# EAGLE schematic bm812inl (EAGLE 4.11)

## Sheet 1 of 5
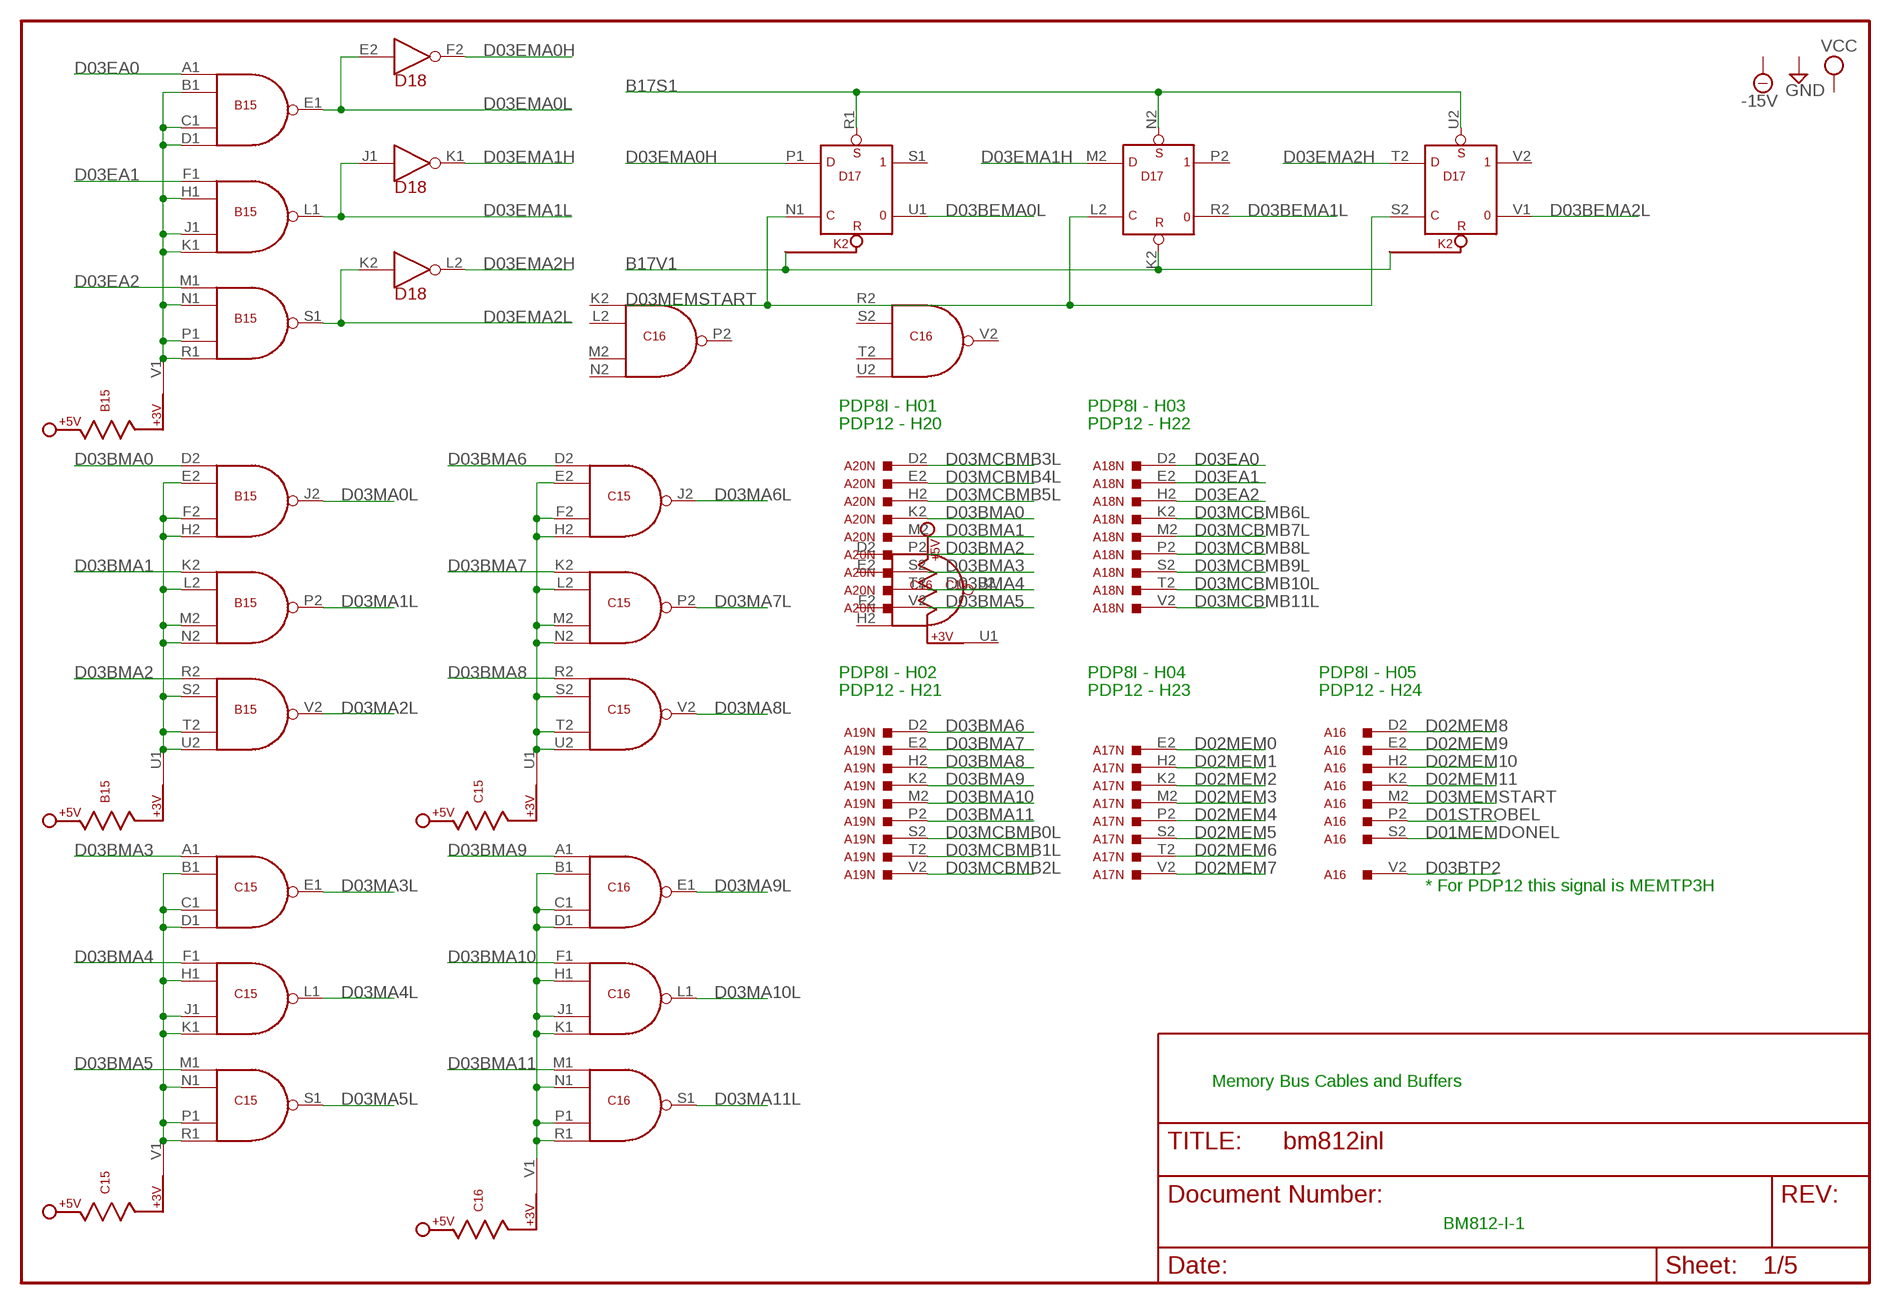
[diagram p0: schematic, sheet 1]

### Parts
A16  M903  [H807]
A17N  M903  [H807]
A18N  M903  [H807]
A19N  M903  [H807]
A20N  M903  [H807]
B15  M627  [H807]
C15  M627  [H807]
C16  M627  [H807]
D17  M206X  [H807]
D18  M111  [H807]

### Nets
B17S1: D17.N2(K2:S) D17.R1(K2B:S) D17.U2(K2C:S) ; also sheet 3,4
B17V1: D17.K2(K2:R) ; also sheet 3,4
D01MEMDONEL: A16.S2 ; also sheet 4
D01STROBEL: A16.P2 ; also sheet 4
D02MEM0: A17N.E2 ; also sheet 3
D02MEM1: A17N.H2 ; also sheet 3
D02MEM2: A17N.K2 ; also sheet 3
D02MEM3: A17N.M2 ; also sheet 3
D02MEM4: A17N.P2 ; also sheet 3
D02MEM5: A17N.S2 ; also sheet 3
D02MEM6: A17N.T2 ; also sheet 3
D02MEM7: A17N.V2 ; also sheet 3
D02MEM8: A16.D2 ; also sheet 3
D02MEM9: A16.E2 ; also sheet 3
D02MEM10: A16.H2 ; also sheet 3
D02MEM11: A16.K2 ; also sheet 3
D03BEMA0L: D17.U1 ; also sheet 5
D03BEMA1L: D17.R2 ; also sheet 5
D03BEMA2L: D17.V1 ; also sheet 5
D03BMA0: A20N.K2 B15.D2(IN1)
D03BMA1: A20N.M2 B15.K2(IN1)
D03BMA2: A20N.P2 B15.R2(IN1)
D03BMA3: A20N.S2 C15.A1(IN1)
D03BMA4: A20N.T2 C15.F1(IN1)
D03BMA5: A20N.V2 C15.M1(IN1)
D03BMA6: A19N.D2 C15.D2(IN1)
D03BMA7: A19N.E2 C15.K2(IN1)
D03BMA8: A19N.H2 C15.R2(IN1)
D03BMA9: A19N.K2 C16.A1(IN1)
D03BMA10: A19N.M2 C16.F1(IN1)
D03BMA11: A19N.P2 C16.M1(IN1)
D03BTP2: A16.V2 ; also sheet 4
D03EA0: A18N.D2 B15.A1(IN1)
D03EA1: A18N.E2 B15.F1(IN1)
D03EA2: A18N.H2 B15.M1(IN1)
D03EMA0H: D17.P1(K2B:D) D18.F2(5:OUT) ; also sheet 4
D03EMA0L: B15.E1(OUT) D18.E2(5:IN) ; also sheet 4
D03EMA1H: D17.M2(K2:D) D18.K1(6:OUT) ; also sheet 4
D03EMA1L: B15.L1(OUT) D18.J1(6:IN) ; also sheet 4
D03EMA2H: D17.T2(K2C:D) D18.L2(9:OUT) ; also sheet 4
D03EMA2L: B15.S1(OUT) D18.K2(9:IN) ; also sheet 4
D03MA0L: B15.J2(OUT) ; also sheet 5
D03MA1L: B15.P2(OUT) ; also sheet 5
D03MA2L: B15.V2(OUT) ; also sheet 5
D03MA3L: C15.E1(OUT) ; also sheet 5
D03MA4L: C15.L1(OUT) ; also sheet 5
D03MA5L: C15.S1(OUT) ; also sheet 5
D03MA6L: C15.J2(OUT) ; also sheet 5
D03MA7L: C15.P2(OUT) ; also sheet 5
D03MA8L: C15.V2(OUT) ; also sheet 5
D03MA9L: C16.E1(OUT) ; also sheet 5
D03MA10L: C16.L1(OUT) ; also sheet 5
D03MA11L: C16.S1(OUT) ; also sheet 5
D03MCBMB0L: A19N.S2 ; also sheet 3
D03MCBMB1L: A19N.T2 ; also sheet 3
D03MCBMB2L: A19N.V2 ; also sheet 3
D03MCBMB3L: A20N.D2 ; also sheet 3
D03MCBMB4L: A20N.E2 ; also sheet 3
D03MCBMB5L: A20N.H2 ; also sheet 3
D03MCBMB6L: A18N.K2 ; also sheet 3
D03MCBMB7L: A18N.M2 ; also sheet 3
D03MCBMB8L: A18N.P2 ; also sheet 3
D03MCBMB9L: A18N.S2 ; also sheet 3
D03MCBMB10L: A18N.T2 ; also sheet 3
D03MCBMB11L: A18N.V2 ; also sheet 3
D03MEMSTART: A16.M2 D17.L2(K2:C) D17.N1(K2B:C) D17.S2(K2C:C) ; also sheet 4
N$1: B15.B1(IN2) B15.C1(IN3) B15.D1(IN4) B15.H1(IN2) B15.J1(IN3) B15.K1(IN4) B15.N1(IN2) B15.P1(IN3) B15.R1(IN4) B15.V1
N$2: B15.E2(IN2) B15.F2(IN3) B15.H2(IN4) B15.L2(IN2) B15.M2(IN3) B15.N2(IN4) B15.S2(IN2) B15.T2(IN3) B15.U1 B15.U2(IN4)
N$4: C15.B1(IN2) C15.C1(IN3) C15.D1(IN4) C15.H1(IN2) C15.J1(IN3) C15.K1(IN4) C15.N1(IN2) C15.P1(IN3) C15.R1(IN4) C15.V1
N$6: C15.E2(IN2) C15.F2(IN3) C15.H2(IN4) C15.L2(IN2) C15.M2(IN3) C15.N2(IN4) C15.S2(IN2) C15.T2(IN3) C15.U1 C15.U2(IN4)
N$122: C16.B1(IN2) C16.C1(IN3) C16.D1(IN4) C16.H1(IN2) C16.J1(IN3) C16.K1(IN4) C16.N1(IN2) C16.P1(IN3) C16.R1(IN4) C16.V1
Unconnected: A16.B1 A16.D1 A16.E1 A16.H1 A16.J1 A16.L1 A16.M1 A16.P1 A16.S1 A16.T2 A17N.B1 A17N.D1 A17N.D2 A17N.E1 A17N.H1 A17N.J1 A17N.L1 A17N.M1 A17N.P1 A17N.S1 A18N.B1 A18N.D1 A18N.E1 A18N.H1 A18N.J1 A18N.L1 A18N.M1 A18N.P1 A18N.S1 A19N.B1 A19N.D1 A19N.E1 A19N.H1 A19N.J1 A19N.L1 A19N.M1 A19N.P1 A19N.S1 A20N.B1 A20N.D1 A20N.E1 A20N.H1 A20N.J1 A20N.L1 A20N.M1 A20N.P1 A20N.S1 D17.D2(A1B:C) D17.E2(A1B:D) D17.F2(A1B:S) D17.H1(A1C:C) D17.H2 D17.J1(A1C:D) D17.J2 D17.K1(A1C:S) D17.L1 D17.M1 D18.L1(8:IN) D18.M1(8:OUT) D18.N1(10:IN) D18.P1(10:OUT) D18.P2(13:IN) D18.R2(13:OUT) D18.S2(15:IN) D18.T2(15:OUT) D18.U1(14:OUT) D18.U2(16:IN) D18.V1(14:IN) D18.V2(16:OUT)

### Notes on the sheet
- PDP8I - H01 | PDP8I - H03
- PDP12 - H20 | PDP12 - H22
- PDP8I - H02 | PDP8I - H04 | PDP8I - H05
- PDP12 - H21 | PDP12 - H23 | PDP12 - H24
- * For PDP12 this signal is MEMTP3H
- Memory Bus Cables and Buffers
- BM812-I-1

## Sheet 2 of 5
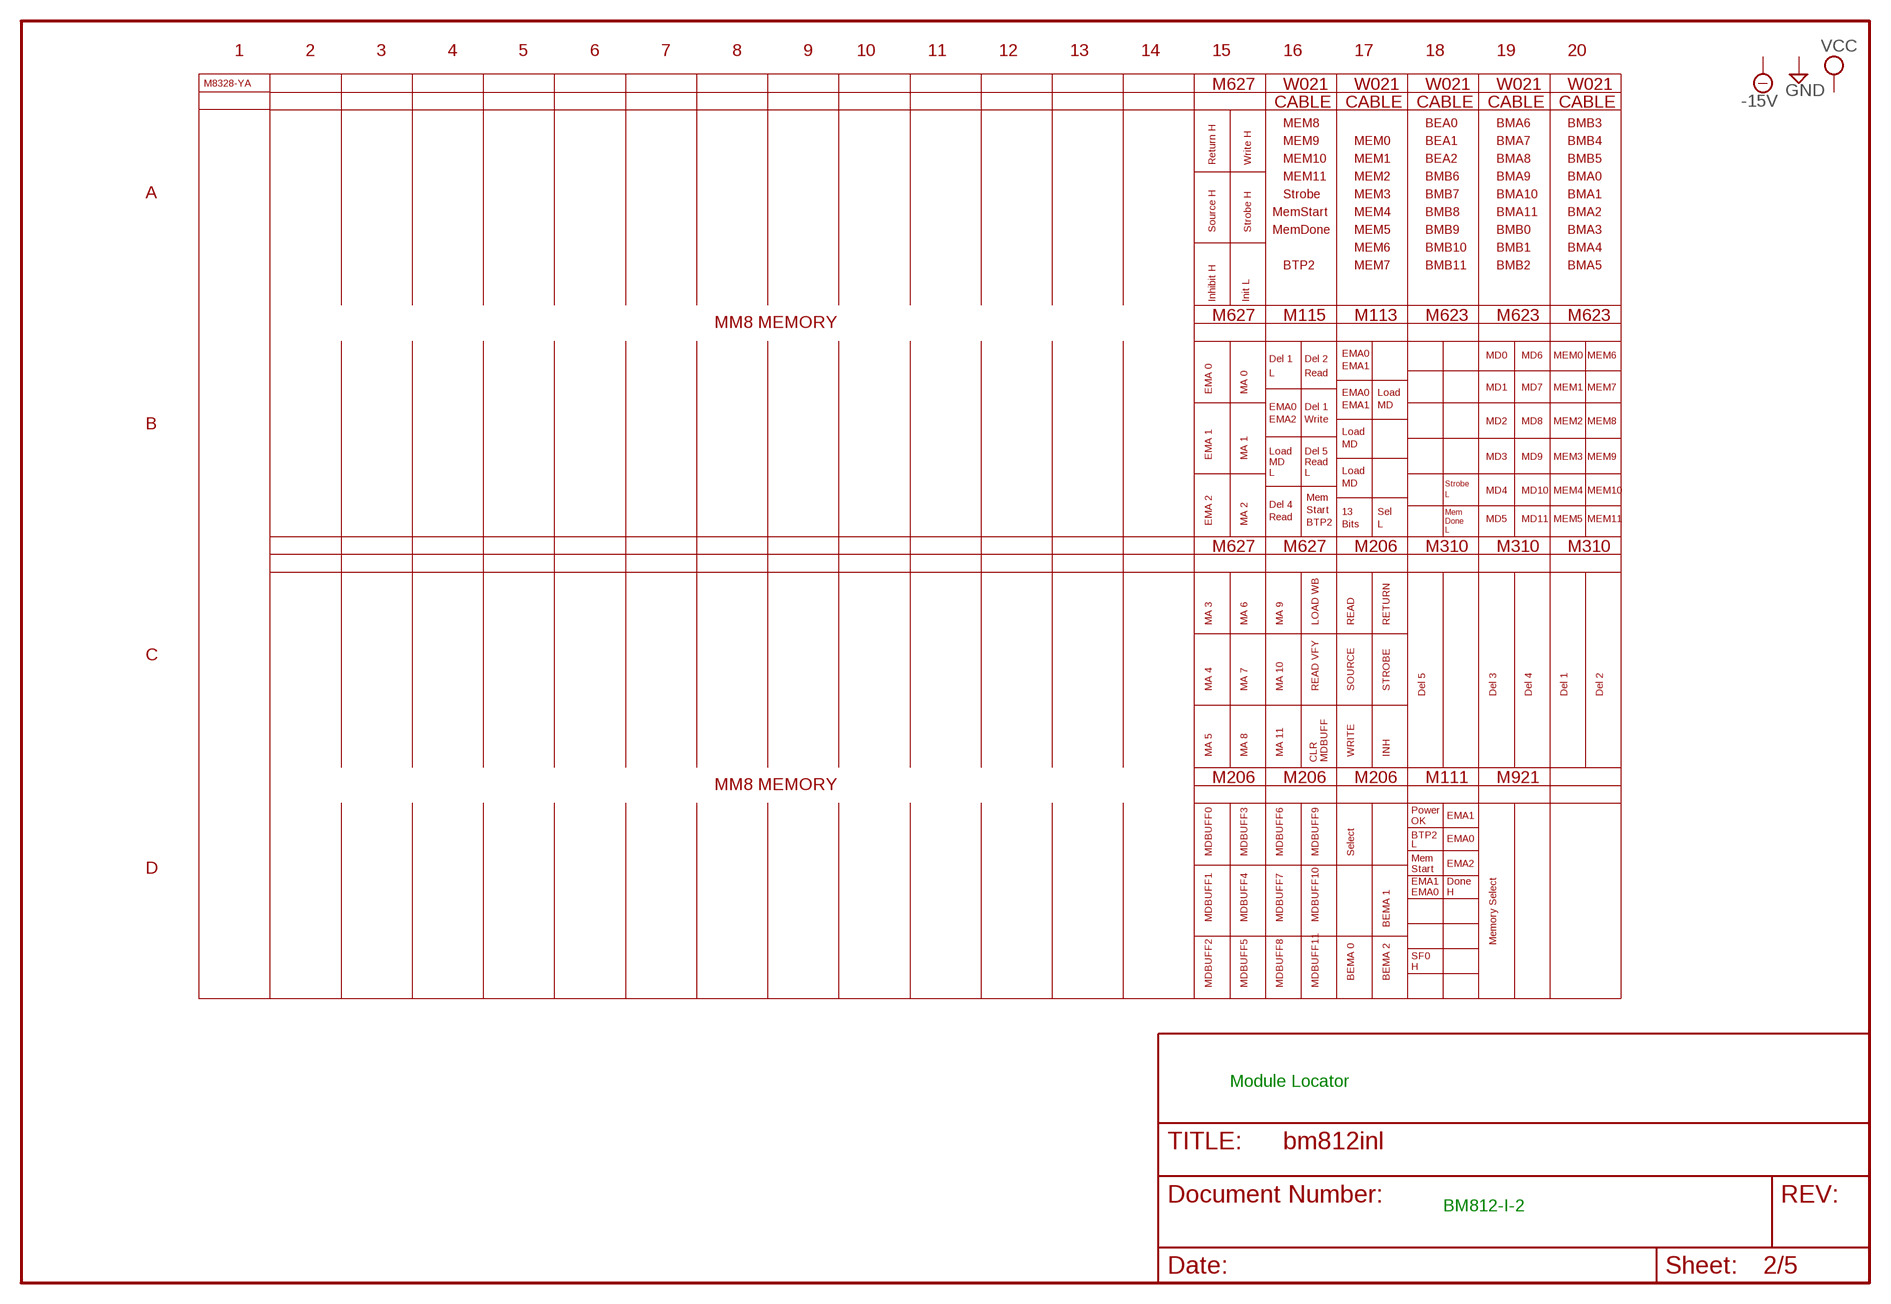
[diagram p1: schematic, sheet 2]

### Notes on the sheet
- 1 | 2 | 3 | 4 | 5 | 6 | 7 | 8 | 9 | 10 | 11 | 12 | 13 | 14 | 15 | 16 | 17 | 18 | 19 | 20
- M8328-YA
- M627 | W021 | W021 | W021 | W021 | W021
- CABLE | CABLE | CABLE | CABLE | CABLE
- MEM8 | BEA0 | BMA6 | BMB3
- MEM9 | MEM0 | BEA1 | BMA7 | BMB4
- Return H | Write H | MEM10 | MEM1 | BEA2 | BMA8 | BMB5
- MEM11 | MEM2 | BMB6 | BMA9 | BMA0
- A | Strobe | MEM3 | BMB7 | BMA10 | BMA1
- MemStart | MEM4 | BMB8 | BMA11 | BMA2
- Source H | Strobe H | MemDone | MEM5 | BMB9 | BMB0 | BMA3
- MEM6 | BMB10 | BMB1 | BMA4
- BTP2 | MEM7 | BMB11 | BMB2 | BMA5
- Inhibit H | Init L
- M627 | M115 | M113 | M623 | M623 | M623
- MM8 MEMORY
- EMA0 | MD0 | MD6 | MEM0 | MEM6
- Del 1 | Del 2
- EMA1
- L | Read
- MD1 | MD7 | MEM1 | MEM7
- EMA 0 | MA 0 | EMA0 | Load
- EMA0 | Del 1 | EMA1 | MD
- EMA2 | Write | MD2 | MD8 | MEM2 | MEM8
- B
- Load
- MD
- Load | Del 5
- EMA 1 | MA 1 | MD3 | MD9 | MEM3 | MEM9
- MD | Read
- L | L | Load
- MD | Strobe
- MD4 | MD10 | MEM4 | MEM10
- L
- Mem
- Del 4
- Start | 13 | Sel | Mem
- Read | MD5 | MD11 | MEM5 | MEM11
- EMA 2 | MA 2 | BTP2 | Done
- Bits | L
- L
- M627 | M627 | M206 | M310 | M310 | M310
- MA 3 | MA 6 | MA 9 | LOAD WB | READ | RETURN
- C
- MA 4 | MA 7 | MA 10 | READ VFY | SOURCE | STROBE
- Del 5 | Del 3 | Del 4 | Del 1 | Del 2
- MA 5 | MA 8 | MA 11 | WRITE | INH
- CLR | MDBUFF
- M206 | M206 | M206 | M111 | M921
- MM8 MEMORY
- Power
- EMA1
- OK
- BTP2
- EMA0
- L
- MDBUFF0 | MDBUFF3 | MDBUFF6 | MDBUFF9 | Select
- Mem
- EMA2
- D | Start
- EMA1 | Done
- EMA0 | H
- MDBUFF1 | MDBUFF4 | MDBUFF7 | MDBUFF10
- BEMA 1
- Memory Select
- SF0
- H
- BEMA 0 | BEMA 2
- MDBUFF2 | MDBUFF5 | MDBUFF8 | MDBUFF11
- Module Locator
- BM812-I-2

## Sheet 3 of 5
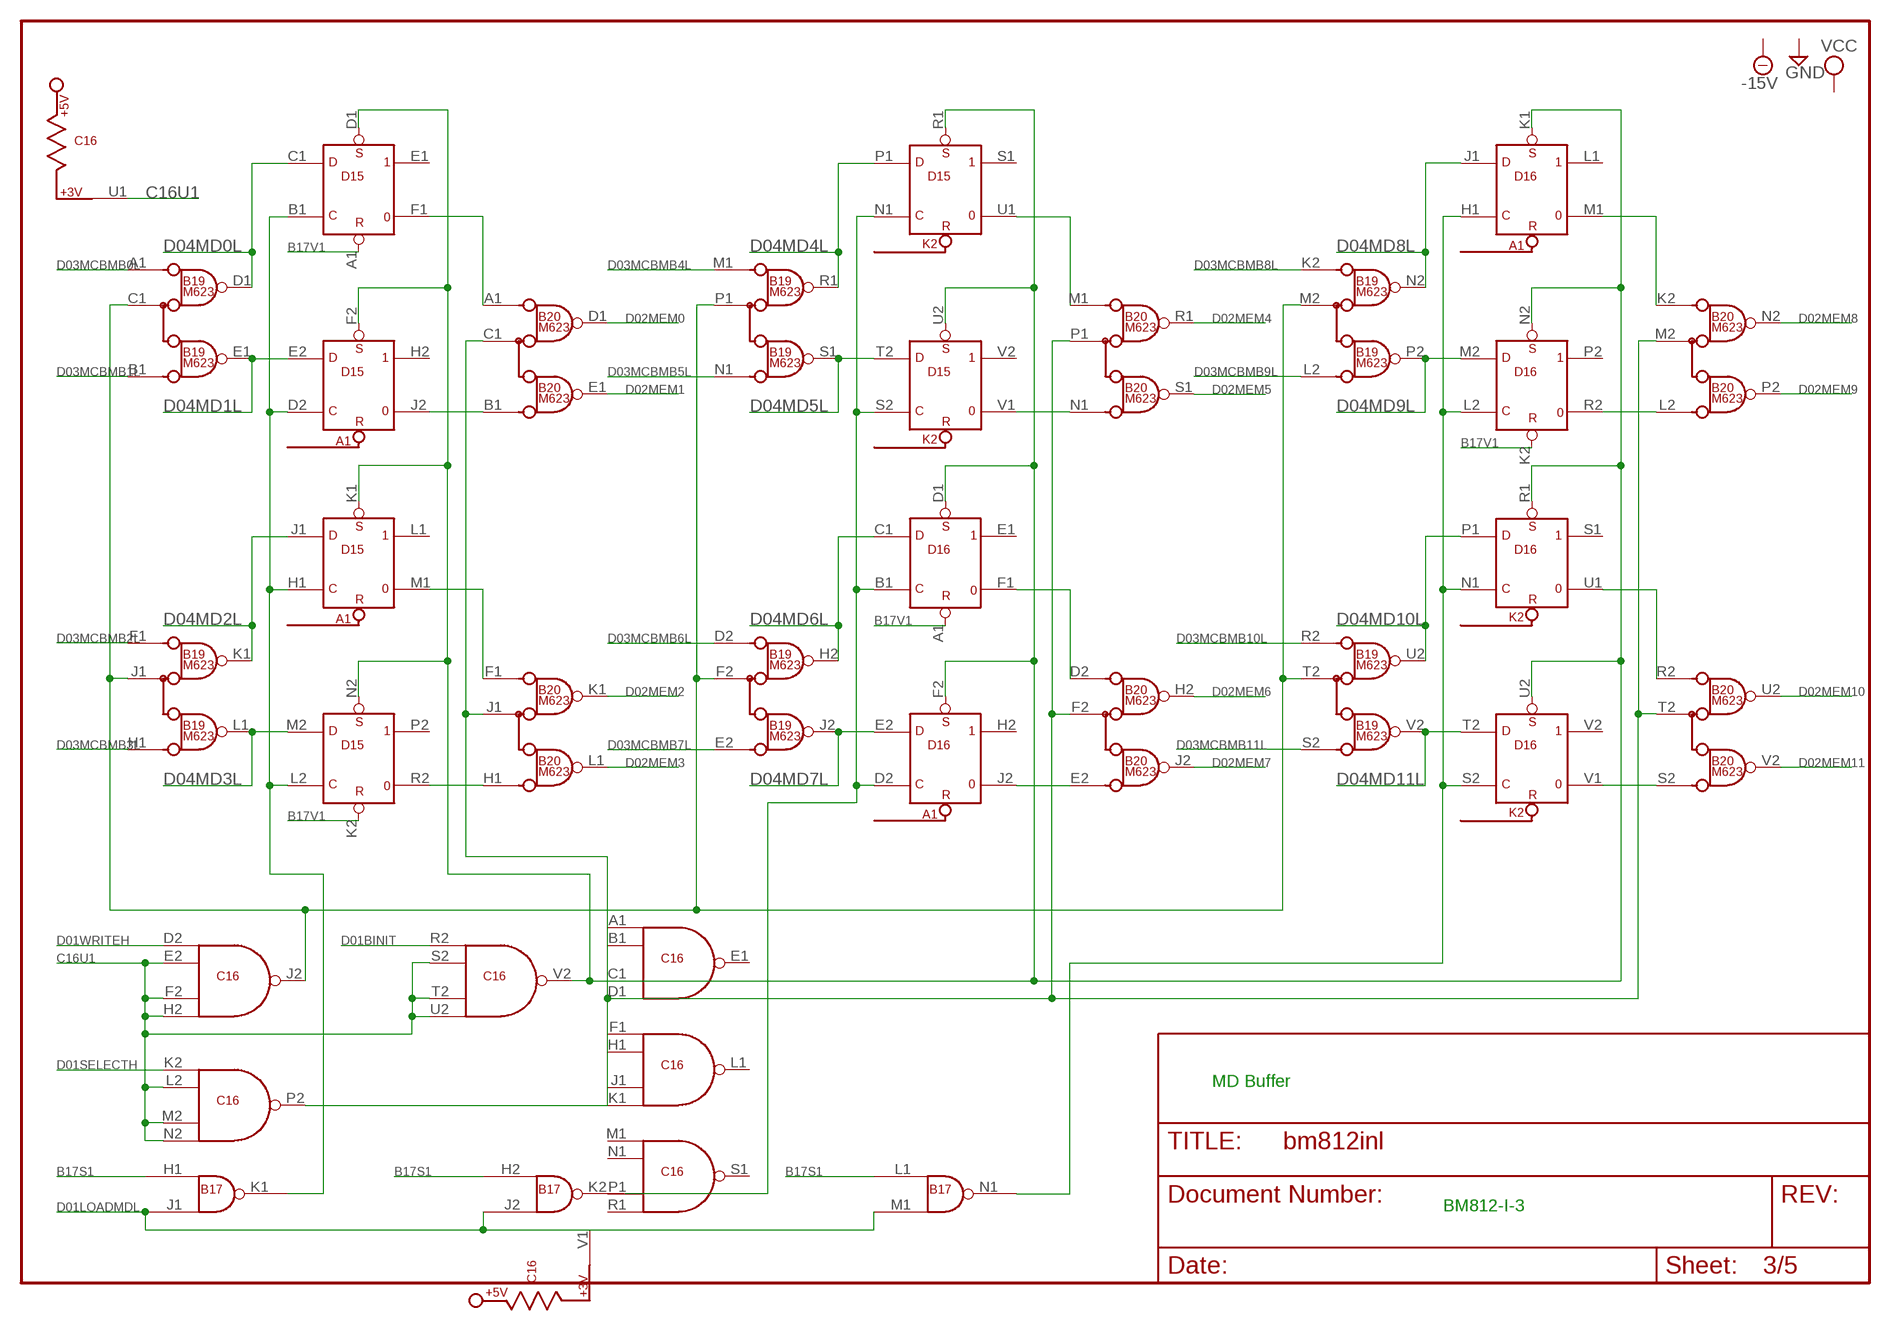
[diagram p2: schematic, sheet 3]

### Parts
B17  M113  [H807]
B19  M623  [H807]
B20  M623  [H807]
D15  M206X  [H807]
D16  M206X  [H807]

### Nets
B17S1: B17.H1(IN1) B17.H2(IN1) B17.L1(IN1) ; also sheet 1,4
B17V1: D15.A1(A1:R) D15.K2(K2:R) D16.A1(A1:R) D16.K2(K2:R) ; also sheet 1,4
C16U1: C16.E2(IN2) C16.F2(IN3) C16.H2(IN4) C16.L2(IN2) C16.M2(IN3) C16.N2(IN4) C16.S2(IN2) C16.T2(IN3) C16.U1 C16.U2(IN4)
D01BINIT: C16.R2(IN1) ; also sheet 4
D01LOADMDL: B17.J1(IN2) B17.J2(IN2) B17.M1(IN2) ; also sheet 4
D01SELECTH: C16.K2(IN1) ; also sheet 4
D01WRITEH: C16.D2(IN1) ; also sheet 4
D02MEM0: B20.D1(D) ; also sheet 1
D02MEM1: B20.E1(E) ; also sheet 1
D02MEM2: B20.K1(D) ; also sheet 1
D02MEM3: B20.L1(E) ; also sheet 1
D02MEM4: B20.R1(D) ; also sheet 1
D02MEM5: B20.S1(E) ; also sheet 1
D02MEM6: B20.H2(D) ; also sheet 1
D02MEM7: B20.J2(E) ; also sheet 1
D02MEM8: B20.N2(D) ; also sheet 1
D02MEM9: B20.P2(E) ; also sheet 1
D02MEM10: B20.U2(D) ; also sheet 1
D02MEM11: B20.V2(E) ; also sheet 1
D03MCBMB0L: B19.A1(A) ; also sheet 1
D03MCBMB1L: B19.B1(B) ; also sheet 1
D03MCBMB2L: B19.F1(A) ; also sheet 1
D03MCBMB3L: B19.H1(B) ; also sheet 1
D03MCBMB4L: B19.M1(A) ; also sheet 1
D03MCBMB5L: B19.N1(B) ; also sheet 1
D03MCBMB6L: B19.D2(A) ; also sheet 1
D03MCBMB7L: B19.E2(B) ; also sheet 1
D03MCBMB8L: B19.K2(A) ; also sheet 1
D03MCBMB9L: B19.L2(B) ; also sheet 1
D03MCBMB10L: B19.R2(A) ; also sheet 1
D03MCBMB11L: B19.S2(B) ; also sheet 1
D04MD0L: B19.D1(D) D15.C1(A1:D) ; also sheet 5
D04MD1L: B19.E1(E) D15.E2(A1B:D) ; also sheet 5
D04MD2L: B19.K1(D) D15.J1(A1C:D) ; also sheet 5
D04MD3L: B19.L1(E) D15.M2(K2:D) ; also sheet 5
D04MD4L: B19.R1(D) D15.P1(K2B:D) ; also sheet 5
D04MD5L: B19.S1(E) D15.T2(K2C:D) ; also sheet 5
D04MD6L: B19.H2(D) D16.C1(A1:D) ; also sheet 5
D04MD7L: B19.J2(E) D16.E2(A1B:D) ; also sheet 5
D04MD8L: B19.N2(D) D16.J1(A1C:D) ; also sheet 5
D04MD9L: B19.P2(E) D16.M2(K2:D) ; also sheet 5
D04MD10L: B19.U2(D) D16.P1(K2B:D) ; also sheet 5
D04MD11L: B19.V2(E) D16.T2(K2C:D) ; also sheet 5
N$8: B17.K1(OUT) D15.B1(A1:C) D15.D2(A1B:C) D15.H1(A1C:C) D15.L2(K2:C)
N$12: B20.H1(B) D15.R2
N$14: B20.A1(A) D15.F1
N$15: B20.B1(B) D15.J2
N$16: B17.K2(OUT) D15.N1(K2B:C) D15.S2(K2C:C) D16.B1(A1:C) D16.D2(A1B:C)
N$17: B20.F1(A) D15.M1
N$20: B19.C1(C) B19.F2(C) B19.J1(C) B19.M2(C) B19.P1(C) B19.T2(C) C16.J2(OUT)
N$21: C16.V2(OUT) D15.D1(A1:S) D15.F2(A1B:S) D15.K1(A1C:S) D15.N2(K2:S) D15.R1(K2B:S) D15.U2(K2C:S) D16.D1(A1:S) D16.F2(A1B:S) D16.K1(A1C:S) D16.N2(K2:S) D16.R1(K2B:S) D16.U2(K2C:S)
N$22: B20.C1(C) B20.F2(C) B20.J1(C) B20.M2(C) B20.P1(C) B20.T2(C) C16.P2(OUT)
N$24: B20.N1(B) D15.V1
N$25: B20.E2(B) D16.J2
N$26: B20.D2(A) D16.F1
N$27: B20.M1(A) D15.U1
N$29: B20.S2(B) D16.V1
N$30: B20.R2(A) D16.U1
N$41: B17.N1(OUT) D16.H1(A1C:C) D16.L2(K2:C) D16.N1(K2B:C) D16.S2(K2C:C)
N$67: B20.L2(B) D16.R2
N$68: B20.K2(A) D16.M1
Unconnected: B17.D2(IN1) B17.E2(IN2) B17.F2(OUT) B17.L2(IN1) B17.M2(IN2) B17.N2(OUT) B17.P2(IN1) B17.R2(IN2) B17.S2(OUT) D15.E1 D15.H2 D15.L1 D15.P2 D15.S1 D15.V2 D16.E1 D16.H2 D16.L1 D16.P2 D16.S1 D16.V2

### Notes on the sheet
- MD Buffer
- BM812-I-3

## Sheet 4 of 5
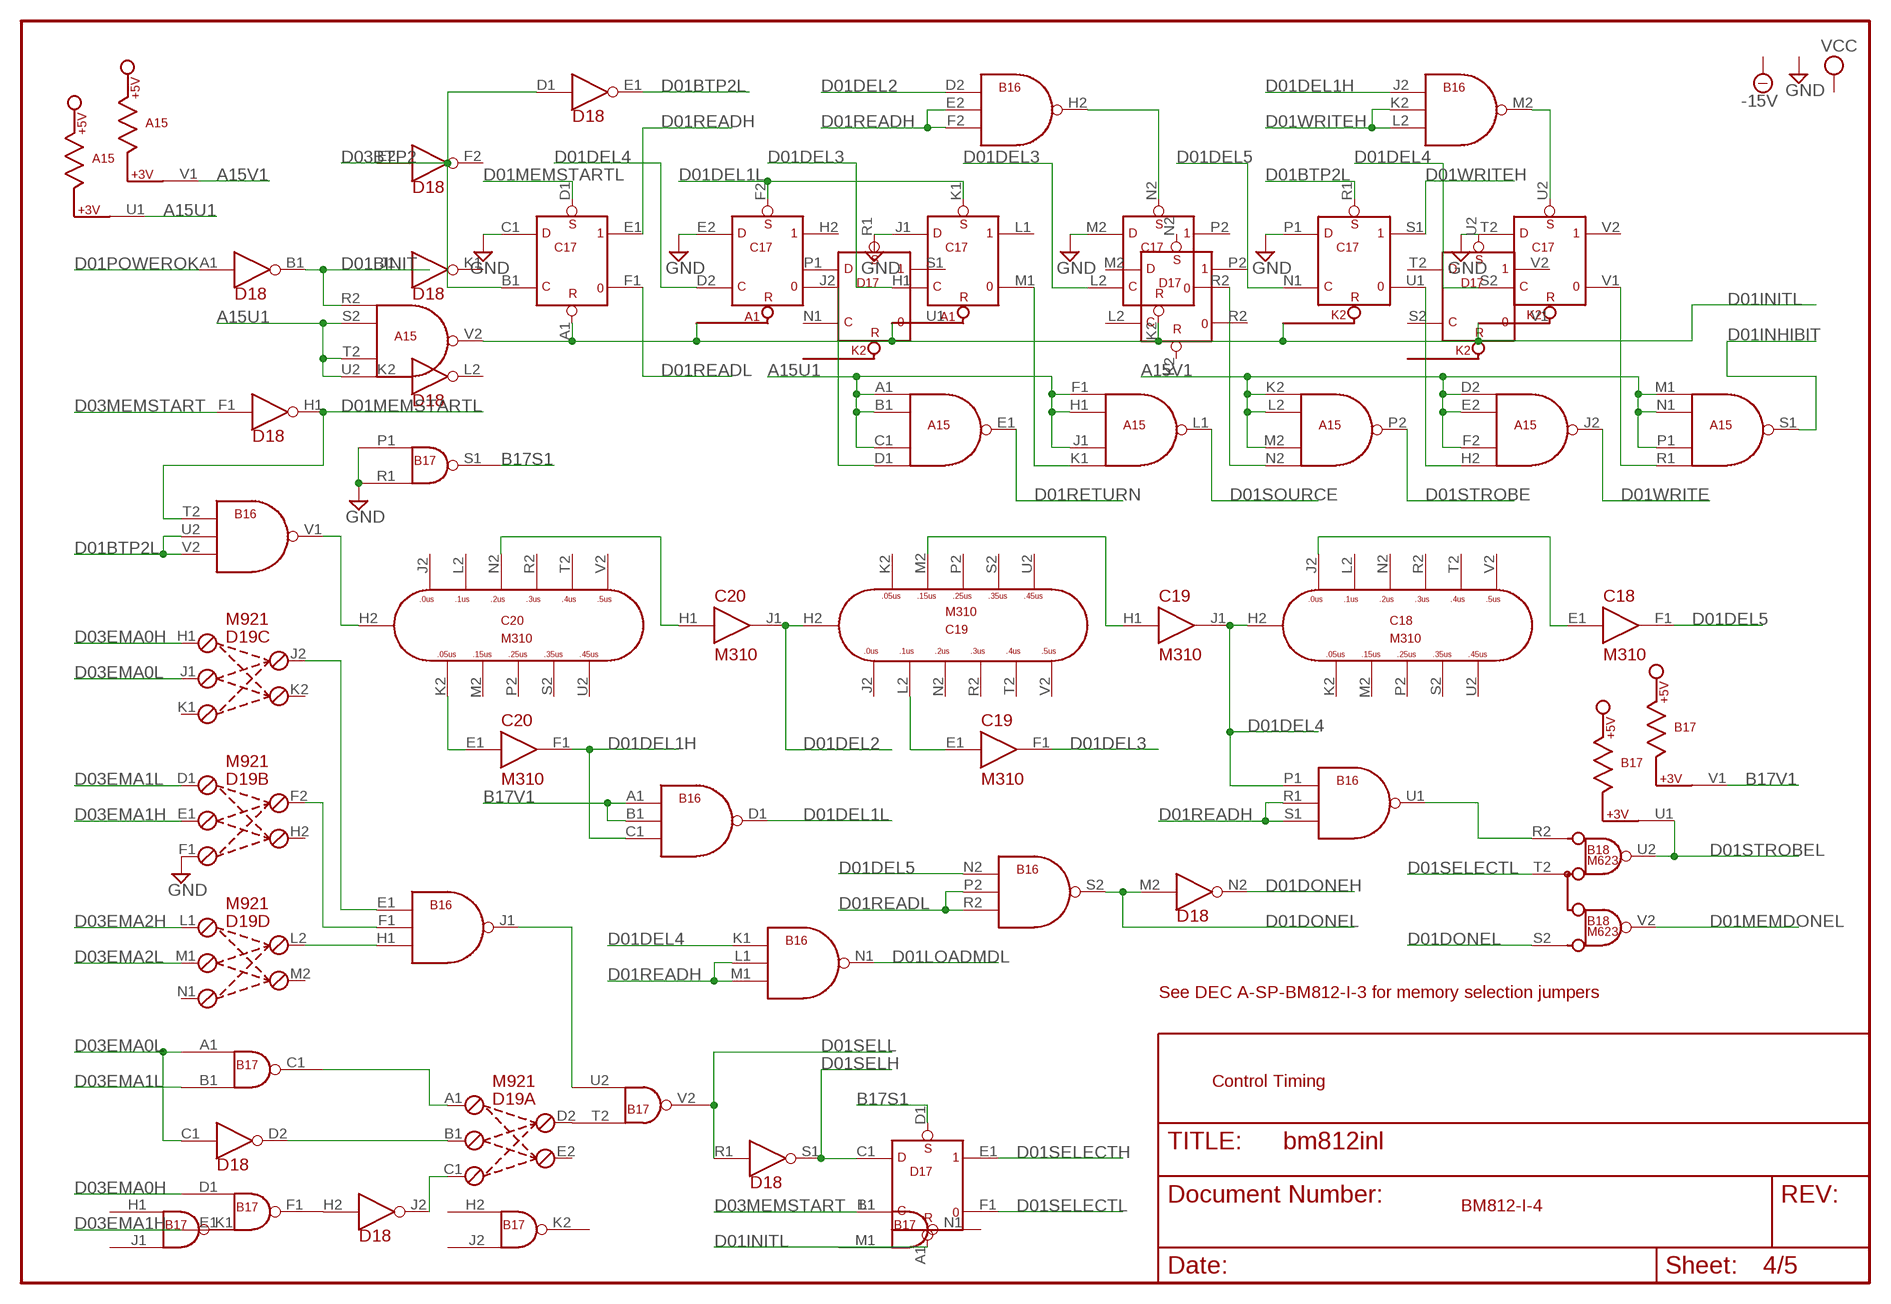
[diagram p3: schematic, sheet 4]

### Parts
A15  M627  [H807]
B16  M115  [H807]
B18  M623  [H807]
C17  M206X  [H807]
C18  M310  [H807]
C19  M310  [H807]
C20  M310  [H807]
D19  M921  [H807]

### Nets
A15U1: A15.A1(IN1) A15.B1(IN2) A15.C1(IN3) A15.F1(IN1) A15.H1(IN2) A15.J1(IN3) A15.S2(IN2) A15.T2(IN3) A15.U1 A15.U2(IN4) ; also sheet 5
A15V1: A15.D2(IN1) A15.E2(IN2) A15.F2(IN3) A15.K2(IN1) A15.L2(IN2) A15.M1(IN1) A15.M2(IN3) A15.N1(IN2) A15.P1(IN3) A15.V1
B17S1: B17.S1(OUT) D17.D1(A1:S) ; also sheet 1,3
B17V1: B16.A1(IN1) B16.B1(IN2) B17.V1 ; also sheet 1,3
D01BINIT: A15.R2(IN1) D18.B1(1:OUT) ; also sheet 3
D01BTP2L: B16.U2(IN2) B16.V2(IN3) C17.R1(K2B:S) D18.E1(3:OUT)
D01DEL1H: B16.C1(IN3) B16.J2(IN1) C20.F1(OUT)
D01DEL1L: B16.D1(OUT) C17.F2(A1B:S) C17.K1(A1C:S)
D01DEL2: B16.D2(IN1) C19.H2 C20.J1(OUT)
D01DEL3: C17.H1(A1C:C) C17.L2(K2:C) C19.F1(OUT)
D01DEL4: B16.K1(IN1) B16.P1(IN1) C17.D2(A1B:C) C17.S2(K2C:C) C18.H2 C19.J1(OUT)
D01DEL5: B16.N2(IN1) C17.N1(K2B:C) C18.F1(OUT)
D01DONEH: D18.N2(11:OUT) ; also sheet 5
D01DONEL: B16.S2(OUT) B18.S2(B) D18.M2(11:IN)
D01INHIBIT: A15.S1(OUT) ; also sheet 5
D01INITL: A15.V2(OUT) C17.A1(A1:R) C17.K2(K2:R) D17.A1(A1:R)
D01LOADMDL: B16.N1(OUT) ; also sheet 3
D01MEMDONEL: B18.V2(E) ; also sheet 1
D01MEMSTARTL: B16.T2(IN1) C17.D1(A1:S) D18.H1(4:OUT)
D01POWEROK: D18.A1(1:IN) ; also sheet 5
D01READH: B16.E2(IN2) B16.F2(IN3) B16.L1(IN2) B16.M1(IN3) B16.R1(IN2) B16.S1(IN3) C17.E1
D01READL: B16.P2(IN2) B16.R2(IN3) C17.F1 ; also sheet 5
D01RETURN: A15.E1(OUT) ; also sheet 5
D01SELECTH: D17.E1 ; also sheet 3
D01SELECTL: B18.T2(C) D17.F1
D01SELH: D17.C1(A1:D) D18.S1(12:OUT)
D01SELL: B17.V2(OUT) D18.R1(12:IN)
D01SOURCE: A15.L1(OUT) ; also sheet 5
D01STROBE: A15.P2(OUT) ; also sheet 5
D01STROBEL: B17.U1 B18.U2(D) ; also sheet 1
D01WRITE: A15.J2(OUT) ; also sheet 5
D01WRITEH: B16.K2(IN2) B16.L2(IN3) C17.S1 ; also sheet 3
D03BTP2: C17.B1(A1:C) D18.D1(3:IN) ; also sheet 1
D03EMA0H: B17.D1(IN1) D19.H1(C:L1) ; also sheet 1
D03EMA0L: B17.A1(IN1) D18.C1(2:IN) D19.J1(C:L2) ; also sheet 1
D03EMA1H: B17.E1(IN2) D19.E1(B:L2) ; also sheet 1
D03EMA1L: B17.B1(IN2) D19.D1(B:L1) ; also sheet 1
D03EMA2H: D19.L1(D:L1) ; also sheet 1
D03EMA2L: D19.M1(D:L2) ; also sheet 1
D03MEMSTART: D17.B1(A1:C) D18.F1(4:IN) ; also sheet 1
GND [Power]: B17.P1(IN1) B17.R1(IN2) C17.C1(A1:D) C17.E2(A1B:D) C17.J1(A1C:D) C17.M2(K2:D) C17.P1(K2B:D) C17.T2(K2C:D) D19.F1(B:L3) ; also sheet 5
N$34: C19.H1(IN) C19.M2
N$35: B16.V1(OUT) C20.H2
N$46: B16.H2(OUT) C17.N2(K2:S)
N$73: B17.C1(OUT) D19.A1(A:L1)
N$91: C20.E1(IN) C20.K2
N$92: B16.M2(OUT) C17.U2(K2C:S)
N$93: C20.H1(IN) C20.N2
N$94: B16.U1(OUT) B18.R2(A)
N$96: A15.D1(IN4) C17.J2
N$97: C19.E1(IN) C19.L2
N$99: C18.E1(IN) C18.J2
N$100: A15.K1(IN4) C17.M1
N$101: A15.N2(IN4) C17.R2
N$103: D18.D2(2:OUT) D19.B1(A:L2)
N$104: A15.H2(IN4) C17.U1
N$108: B17.F1(OUT) D18.H2(7:IN)
N$109: A15.R1(IN4) C17.V1
N$111: D18.J2(7:OUT) D19.C1(A:L3)
N$112: B17.T2(IN1) D19.D2(A:R1)
N$113: B16.H1(IN3) D19.L2(D:R1)
N$128: B16.F1(IN2) D19.F2(B:R1)
N$129: B16.E1(IN1) D19.J2(C:R1)
N$132: B16.J1(OUT) B17.U2(IN2)
Unconnected: B18.A1(A) B18.B1(B) B18.C1(C) B18.D1(D) B18.D2(A) B18.E1(E) B18.E2(B) B18.F1(A) B18.F2(C) B18.H1(B) B18.H2(D) B18.J1(C) B18.J2(E) B18.K1(D) B18.K2(A) B18.L1(E) B18.L2(B) B18.M1(A) B18.M2(C) B18.N1(B) B18.N2(D) B18.P1(C) B18.P2(E) B18.R1(D) B18.S1(E) C17.H2 C17.L1 C17.P2 C17.V2 C18.H1(IN) C18.J1(OUT) C18.K2 C18.L2 C18.M2 C18.N2 C18.P2 C18.R2 C18.S2 C18.T2 C18.U2 C18.V2 C19.J2 C19.K2 C19.N2 C19.P2 C19.R2 C19.S2 C19.T2 C19.U2 C19.V2 C20.J2 C20.L2 C20.M2 C20.P2 C20.R2 C20.S2 C20.T2 C20.U2 C20.V2 D17.P2 D17.S1 D17.V2 D19.E2(A:R2) D19.H2(B:R2) D19.K1(C:L3) D19.K2(C:R2) D19.M2(D:R2) D19.N1(D:L3) D19.N2(E:R1) D19.P1(E:L1) D19.P2(E:R2) D19.R1(E:L2) D19.R2(F:R2) D19.S1(E:L3) D19.S2(F:L1) D19.T2(F:R1) D19.U1(F:L2) D19.V1(F:L3)

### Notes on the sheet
- See DEC A-SP-BM812-I-3 for memory selection jumpers
- Control Timing
- BM812-I-4

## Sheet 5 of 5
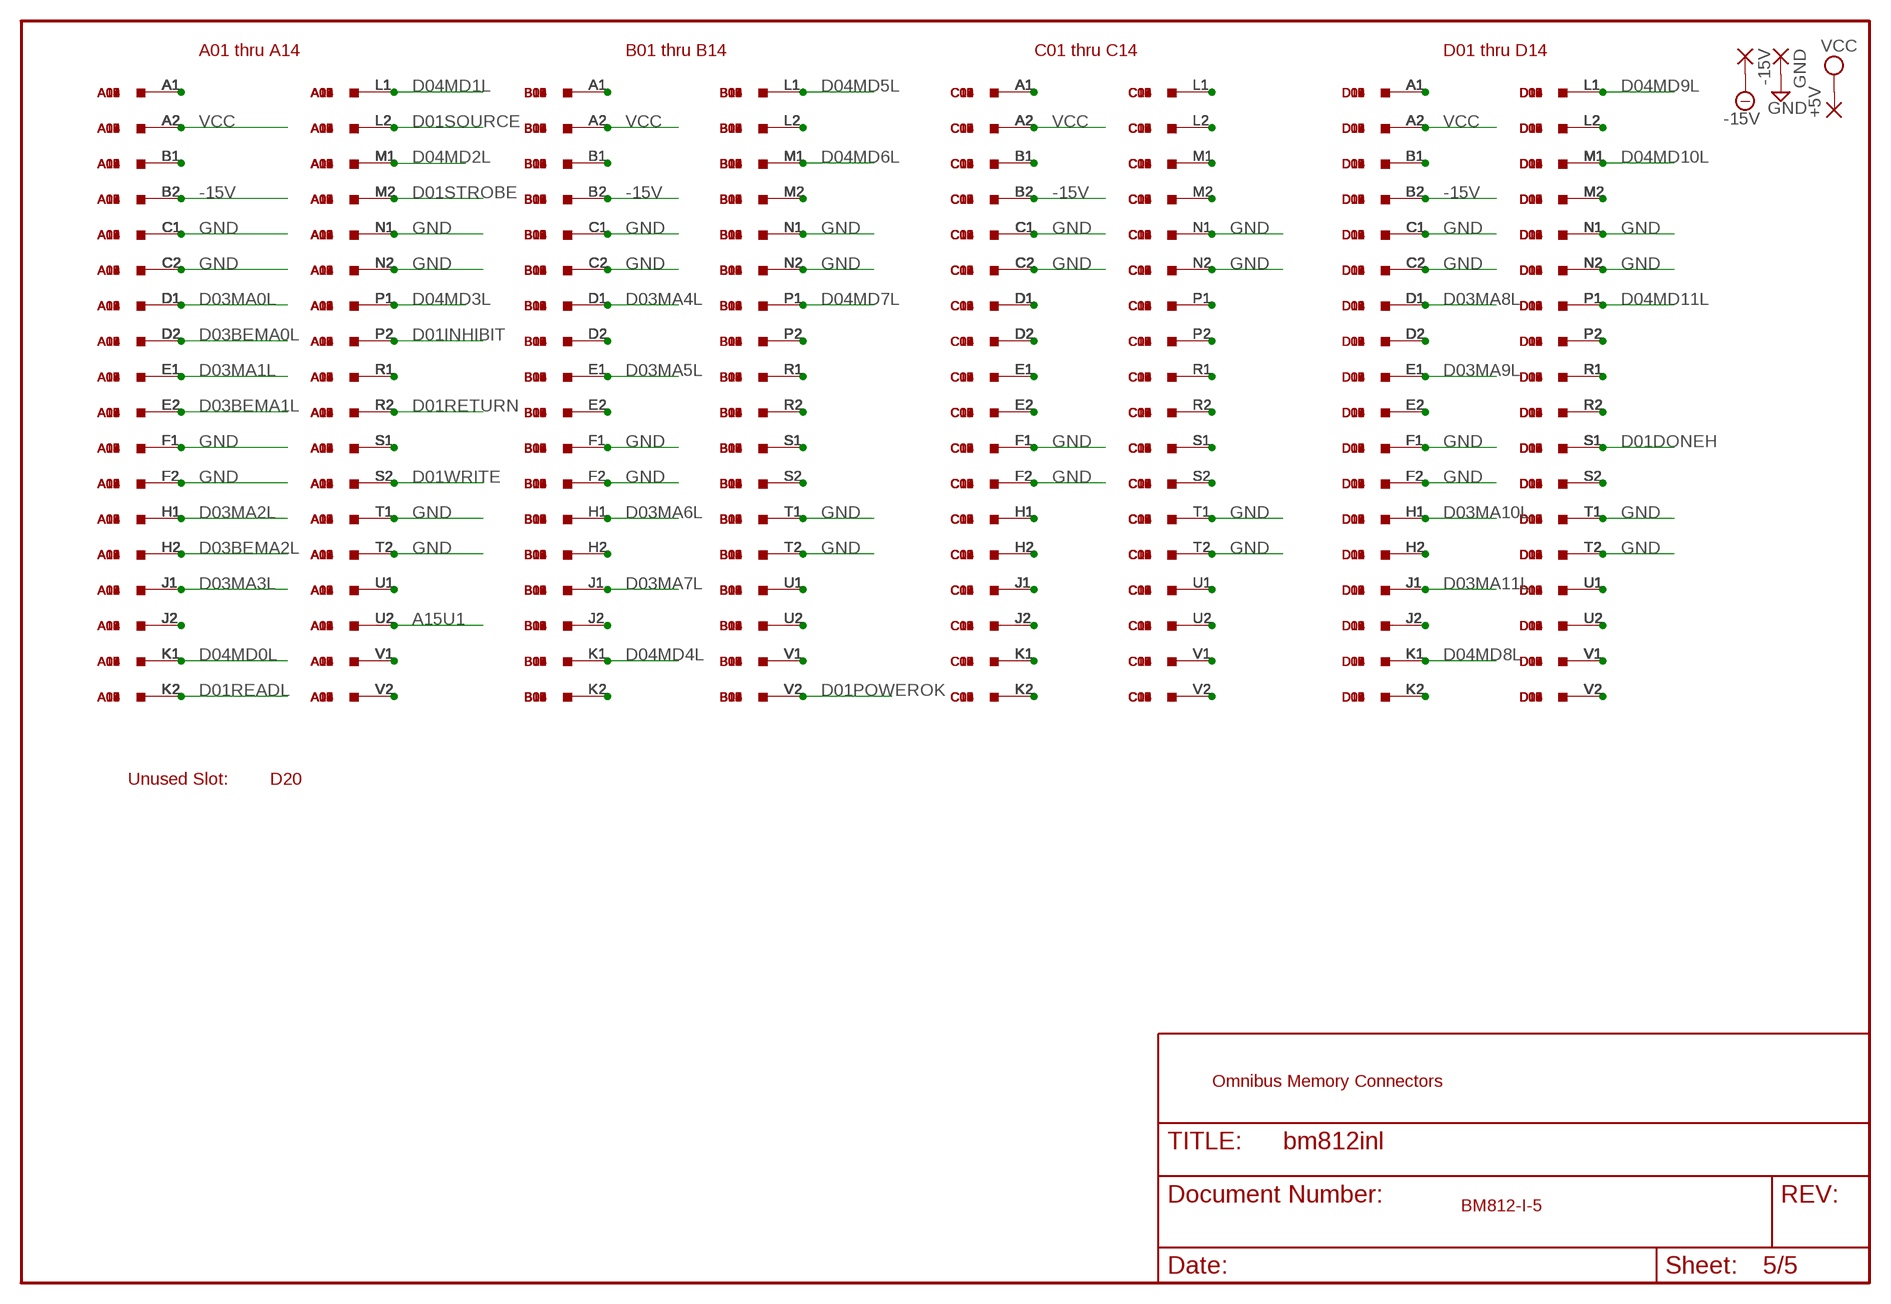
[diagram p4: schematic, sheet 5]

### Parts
+5V  2,54/0,8  [2,54/0,8]
-15V  2,54/0,8  [2,54/0,8]
A01  M916  [H807]
A02  M916  [H807]
A03  M916  [H807]
A04  M916  [H807]
A05  M916  [H807]
A06  M916  [H807]
A07  M916  [H807]
A08  M916  [H807]
A09  M916  [H807]
A10  M916  [H807]
A11  M916  [H807]
A12  M916  [H807]
A13  M916  [H807]
A14  M916  [H807]
B01  M916  [H807]
B02  M916  [H807]
B03  M916  [H807]
B04  M916  [H807]
B05  M916  [H807]
B06  M916  [H807]
B07  M916  [H807]
B08  M916  [H807]
B09  M916  [H807]
B10  M916  [H807]
B11  M916  [H807]
B12  M916  [H807]
B13  M916  [H807]
B14  M916  [H807]
C01  M916  [H807]
C02  M916  [H807]
C03  M916  [H807]
C04  M916  [H807]
C05  M916  [H807]
C06  M916  [H807]
C07  M916  [H807]
C08  M916  [H807]
C09  M916  [H807]
C10  M916  [H807]
C11  M916  [H807]
C12  M916  [H807]
C13  M916  [H807]
C14  M916  [H807]
D01  M916  [H807]
D02  M916  [H807]
D03  M916  [H807]
D04  M916  [H807]
D05  M916  [H807]
D06  M916  [H807]
D07  M916  [H807]
D08  M916  [H807]
D09  M916  [H807]
D10  M916  [H807]
D11  M916  [H807]
D12  M916  [H807]
D13  M916  [H807]
D14  M916  [H807]
D20  H807  [H807]
GND  2,54/0,8  [2,54/0,8]

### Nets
-15V [Power]: -15V.1(P) A01.B2 A02.B2 A03.B2 A04.B2 A05.B2 A06.B2 A07.B2 A08.B2 A09.B2 A10.B2 A11.B2 A12.B2 A13.B2 A14.B2 B01.B2 B02.B2 B03.B2 B04.B2 B05.B2 B06.B2 B07.B2 B08.B2 B09.B2 B10.B2 B11.B2 B12.B2 B13.B2 B14.B2 C01.B2 C02.B2 C03.B2 C04.B2 C05.B2 C06.B2 C07.B2 C08.B2 C09.B2 C10.B2 C11.B2 C12.B2 C13.B2 C14.B2 D01.B2 D02.B2 D03.B2 D04.B2 D05.B2 D06.B2 D07.B2 D08.B2 D09.B2 D10.B2 D11.B2 D12.B2 D13.B2 D14.B2
A15U1: A01.U2 A02.U2 A03.U2 A04.U2 A05.U2 A06.U2 A07.U2 A08.U2 A09.U2 A10.U2 A11.U2 A12.U2 A13.U2 A14.U2 ; also sheet 4
D01DONEH: D01.S1 D02.S1 D03.S1 D04.S1 D05.S1 D06.S1 D07.S1 D08.S1 D09.S1 D10.S1 D11.S1 D12.S1 D13.S1 D14.S1 ; also sheet 4
D01INHIBIT: A01.P2 A02.P2 A03.P2 A04.P2 A05.P2 A06.P2 A07.P2 A08.P2 A09.P2 A10.P2 A11.P2 A12.P2 A13.P2 A14.P2 ; also sheet 4
D01POWEROK: B01.V2 B02.V2 B03.V2 B04.V2 B05.V2 B06.V2 B07.V2 B08.V2 B09.V2 B10.V2 B11.V2 B12.V2 B13.V2 B14.V2 ; also sheet 4
D01READL: A01.K2 A02.K2 A03.K2 A04.K2 A05.K2 A06.K2 A07.K2 A08.K2 A09.K2 A10.K2 A11.K2 A12.K2 A13.K2 A14.K2 ; also sheet 4
D01RETURN: A01.R2 A02.R2 A03.R2 A04.R2 A05.R2 A06.R2 A07.R2 A08.R2 A09.R2 A10.R2 A11.R2 A12.R2 A13.R2 A14.R2 ; also sheet 4
D01SOURCE: A01.L2 A02.L2 A03.L2 A04.L2 A05.L2 A06.L2 A07.L2 A08.L2 A09.L2 A10.L2 A11.L2 A12.L2 A13.L2 A14.L2 ; also sheet 4
D01STROBE: A01.M2 A02.M2 A03.M2 A04.M2 A05.M2 A06.M2 A07.M2 A08.M2 A09.M2 A10.M2 A11.M2 A12.M2 A13.M2 A14.M2 ; also sheet 4
D01WRITE: A01.S2 A02.S2 A03.S2 A04.S2 A05.S2 A06.S2 A07.S2 A08.S2 A09.S2 A10.S2 A11.S2 A12.S2 A13.S2 A14.S2 ; also sheet 4
D03BEMA0L: A01.D2 A02.D2 A03.D2 A04.D2 A05.D2 A06.D2 A07.D2 A08.D2 A09.D2 A10.D2 A11.D2 A12.D2 A13.D2 A14.D2 ; also sheet 1
D03BEMA1L: A01.E2 A02.E2 A03.E2 A04.E2 A05.E2 A06.E2 A07.E2 A08.E2 A09.E2 A10.E2 A11.E2 A12.E2 A13.E2 A14.E2 ; also sheet 1
D03BEMA2L: A01.H2 A02.H2 A03.H2 A04.H2 A05.H2 A06.H2 A07.H2 A08.H2 A09.H2 A10.H2 A11.H2 A12.H2 A13.H2 A14.H2 ; also sheet 1
D03MA0L: A01.D1 A02.D1 A03.D1 A04.D1 A05.D1 A06.D1 A07.D1 A08.D1 A09.D1 A10.D1 A11.D1 A12.D1 A13.D1 A14.D1 ; also sheet 1
D03MA1L: A01.E1 A02.E1 A03.E1 A04.E1 A05.E1 A06.E1 A07.E1 A08.E1 A09.E1 A10.E1 A11.E1 A12.E1 A13.E1 A14.E1 ; also sheet 1
D03MA2L: A01.H1 A02.H1 A03.H1 A04.H1 A05.H1 A06.H1 A07.H1 A08.H1 A09.H1 A10.H1 A11.H1 A12.H1 A13.H1 A14.H1 ; also sheet 1
D03MA3L: A01.J1 A02.J1 A03.J1 A04.J1 A05.J1 A06.J1 A07.J1 A08.J1 A09.J1 A10.J1 A11.J1 A12.J1 A13.J1 A14.J1 ; also sheet 1
D03MA4L: B01.D1 B02.D1 B03.D1 B04.D1 B05.D1 B06.D1 B07.D1 B08.D1 B09.D1 B10.D1 B11.D1 B12.D1 B13.D1 B14.D1 ; also sheet 1
D03MA5L: B01.E1 B02.E1 B03.E1 B04.E1 B05.E1 B06.E1 B07.E1 B08.E1 B09.E1 B10.E1 B11.E1 B12.E1 B13.E1 B14.E1 ; also sheet 1
D03MA6L: B01.H1 B02.H1 B03.H1 B04.H1 B05.H1 B06.H1 B07.H1 B08.H1 B09.H1 B10.H1 B11.H1 B12.H1 B13.H1 B14.H1 ; also sheet 1
D03MA7L: B01.J1 B02.J1 B03.J1 B04.J1 B05.J1 B06.J1 B07.J1 B08.J1 B09.J1 B10.J1 B11.J1 B12.J1 B13.J1 B14.J1 ; also sheet 1
D03MA8L: D01.D1 D02.D1 D03.D1 D04.D1 D05.D1 D06.D1 D07.D1 D08.D1 D09.D1 D10.D1 D11.D1 D12.D1 D13.D1 D14.D1 ; also sheet 1
D03MA9L: D01.E1 D02.E1 D03.E1 D04.E1 D05.E1 D06.E1 D07.E1 D08.E1 D09.E1 D10.E1 D11.E1 D12.E1 D13.E1 D14.E1 ; also sheet 1
D03MA10L: D01.H1 D02.H1 D03.H1 D04.H1 D05.H1 D06.H1 D07.H1 D08.H1 D09.H1 D10.H1 D11.H1 D12.H1 D13.H1 D14.H1 ; also sheet 1
D03MA11L: D01.J1 D02.J1 D03.J1 D04.J1 D05.J1 D06.J1 D07.J1 D08.J1 D09.J1 D10.J1 D11.J1 D12.J1 D13.J1 D14.J1 ; also sheet 1
D04MD0L: A01.K1 A02.K1 A03.K1 A04.K1 A05.K1 A06.K1 A07.K1 A08.K1 A09.K1 A10.K1 A11.K1 A12.K1 A13.K1 A14.K1 ; also sheet 3
D04MD1L: A01.L1 A02.L1 A03.L1 A04.L1 A05.L1 A06.L1 A07.L1 A08.L1 A09.L1 A10.L1 A11.L1 A12.L1 A13.L1 A14.L1 ; also sheet 3
D04MD2L: A01.M1 A02.M1 A03.M1 A04.M1 A05.M1 A06.M1 A07.M1 A08.M1 A09.M1 A10.M1 A11.M1 A12.M1 A13.M1 A14.M1 ; also sheet 3
D04MD3L: A01.P1 A02.P1 A03.P1 A04.P1 A05.P1 A06.P1 A07.P1 A08.P1 A09.P1 A10.P1 A11.P1 A12.P1 A13.P1 A14.P1 ; also sheet 3
D04MD4L: B01.K1 B02.K1 B03.K1 B04.K1 B05.K1 B06.K1 B07.K1 B08.K1 B09.K1 B10.K1 B11.K1 B12.K1 B13.K1 B14.K1 ; also sheet 3
D04MD5L: B01.L1 B02.L1 B03.L1 B04.L1 B05.L1 B06.L1 B07.L1 B08.L1 B09.L1 B10.L1 B11.L1 B12.L1 B13.L1 B14.L1 ; also sheet 3
D04MD6L: B01.M1 B02.M1 B03.M1 B04.M1 B05.M1 B06.M1 B07.M1 B08.M1 B09.M1 B10.M1 B11.M1 B12.M1 B13.M1 B14.M1 ; also sheet 3
D04MD7L: B01.P1 B02.P1 B03.P1 B04.P1 B05.P1 B06.P1 B07.P1 B08.P1 B09.P1 B10.P1 B11.P1 B12.P1 B13.P1 B14.P1 ; also sheet 3
D04MD8L: D01.K1 D02.K1 D03.K1 D04.K1 D05.K1 D06.K1 D07.K1 D08.K1 D09.K1 D10.K1 D11.K1 D12.K1 D13.K1 D14.K1 ; also sheet 3
D04MD9L: D01.L1 D02.L1 D03.L1 D04.L1 D05.L1 D06.L1 D07.L1 D08.L1 D09.L1 D10.L1 D11.L1 D12.L1 D13.L1 D14.L1 ; also sheet 3
D04MD10L: D01.M1 D02.M1 D03.M1 D04.M1 D05.M1 D06.M1 D07.M1 D08.M1 D09.M1 D10.M1 D11.M1 D12.M1 D13.M1 D14.M1 ; also sheet 3
D04MD11L: D01.P1 D02.P1 D03.P1 D04.P1 D05.P1 D06.P1 D07.P1 D08.P1 D09.P1 D10.P1 D11.P1 D12.P1 D13.P1 D14.P1 ; also sheet 3
GND [Power]: A01.C1 A01.C2 A01.F1 A01.F2 A01.N1 A01.N2 A01.T1 A01.T2 A02.C1 A02.C2 A02.F1 A02.F2 A02.N1 A02.N2 A02.T1 A02.T2 A03.C1 A03.C2 A03.F1 A03.F2 A03.N1 A03.N2 A03.T1 A03.T2 A04.C1 A04.C2 A04.F1 A04.F2 A04.N1 A04.N2 A04.T1 A04.T2 A05.C1 A05.C2 A05.F1 A05.F2 A05.N1 A05.N2 A05.T1 A05.T2 A06.C1 A06.C2 A06.F1 A06.F2 A06.N1 A06.N2 A06.T1 A06.T2 A07.C1 A07.C2 A07.F1 A07.F2 A07.N1 A07.N2 A07.T1 A07.T2 A08.C1 A08.C2 A08.F1 A08.F2 A08.N1 A08.N2 A08.T1 A08.T2 A09.C1 A09.C2 A09.F1 A09.F2 A09.N1 A09.N2 A09.T1 A09.T2 A10.C1 A10.C2 A10.F1 A10.F2 A10.N1 A10.N2 A10.T1 A10.T2 A11.C1 A11.C2 A11.F1 A11.F2 A11.N1 A11.N2 A11.T1 A11.T2 A12.C1 A12.C2 A12.F1 A12.F2 A12.N1 A12.N2 A12.T1 A12.T2 A13.C1 A13.C2 A13.F1 A13.F2 A13.N1 A13.N2 A13.T1 A13.T2 A14.C1 A14.C2 A14.F1 A14.F2 A14.N1 A14.N2 A14.T1 A14.T2 B01.C1 B01.C2 B01.F1 B01.F2 B01.N1 B01.N2 B01.T1 B01.T2 B02.C1 B02.C2 B02.F1 B02.F2 B02.N1 B02.N2 B02.T1 B02.T2 B03.C1 B03.C2 B03.F1 B03.F2 B03.N1 B03.N2 B03.T1 B03.T2 B04.C1 B04.C2 B04.F1 B04.F2 B04.N1 B04.N2 B04.T1 B04.T2 B05.C1 B05.C2 B05.F1 B05.F2 B05.N1 B05.N2 B05.T1 B05.T2 B06.C1 B06.C2 B06.F1 B06.F2 B06.N1 B06.N2 B06.T1 B06.T2 B07.C1 B07.C2 B07.F1 B07.F2 B07.N1 B07.N2 B07.T1 B07.T2 B08.C1 B08.C2 B08.F1 B08.F2 B08.N1 B08.N2 B08.T1 B08.T2 B09.C1 B09.C2 B09.F1 B09.F2 B09.N1 B09.N2 B09.T1 B09.T2 B10.C1 B10.C2 B10.F1 B10.F2 B10.N1 B10.N2 B10.T1 B10.T2 B11.C1 B11.C2 B11.F1 B11.F2 B11.N1 B11.N2 B11.T1 B11.T2 B12.C1 B12.C2 B12.F1 B12.F2 B12.N1 B12.N2 B12.T1 B12.T2 B13.C1 B13.C2 B13.F1 B13.F2 B13.N1 B13.N2 B13.T1 B13.T2 B14.C1 B14.C2 B14.F1 B14.F2 B14.N1 B14.N2 B14.T1 B14.T2 C01.C1 C01.C2 C01.F1 C01.F2 C01.N1 C01.N2 C01.T1 C01.T2 C02.C1 C02.C2 C02.F1 C02.F2 C02.N1 C02.N2 C02.T1 C02.T2 C03.C1 C03.C2 C03.F1 C03.F2 C03.N1 C03.N2 C03.T1 C03.T2 C04.C1 C04.C2 C04.F1 C04.F2 C04.N1 C04.N2 C04.T1 C04.T2 C05.C1 C05.C2 C05.F1 C05.F2 C05.N1 C05.N2 C05.T1 C05.T2 C06.C1 C06.C2 C06.F1 C06.F2 C06.N1 C06.N2 C06.T1 C06.T2 C07.C1 C07.C2 C07.F1 C07.F2 C07.N1 C07.N2 C07.T1 C07.T2 C08.C1 C08.C2 C08.F1 C08.F2 C08.N1 C08.N2 C08.T1 C08.T2 C09.C1 C09.C2 C09.F1 C09.F2 C09.N1 C09.N2 C09.T1 C09.T2 C10.C1 C10.C2 C10.F1 C10.F2 C10.N1 C10.N2 C10.T1 C10.T2 C11.C1 C11.C2 C11.F1 C11.F2 C11.N1 C11.N2 C11.T1 C11.T2 C12.C1 C12.C2 C12.F1 C12.F2 C12.N1 C12.N2 C12.T1 C12.T2 C13.C1 C13.C2 C13.F1 C13.F2 C13.N1 C13.N2 C13.T1 C13.T2 C14.C1 C14.C2 C14.F1 C14.F2 C14.N1 C14.N2 C14.T1 C14.T2 D01.C1 D01.C2 D01.F1 D01.F2 D01.N1 D01.N2 D01.T1 D01.T2 D02.C1 D02.C2 D02.F1 D02.F2 D02.N1 D02.N2 D02.T1 D02.T2 D03.C1 D03.C2 D03.F1 D03.F2 D03.N1 D03.N2 D03.T1 D03.T2 D04.C1 D04.C2 D04.F1 D04.F2 D04.N1 D04.N2 D04.T1 D04.T2 D05.C1 D05.C2 D05.F1 D05.F2 D05.N1 D05.N2 D05.T1 D05.T2 D06.C1 D06.C2 D06.F1 D06.F2 D06.N1 D06.N2 D06.T1 D06.T2 D07.C1 D07.C2 D07.F1 D07.F2 D07.N1 D07.N2 D07.T1 D07.T2 D08.C1 D08.C2 D08.F1 D08.F2 D08.N1 D08.N2 D08.T1 D08.T2 D09.C1 D09.C2 D09.F1 D09.F2 D09.N1 D09.N2 D09.T1 D09.T2 D10.C1 D10.C2 D10.F1 D10.F2 D10.N1 D10.N2 D10.T1 D10.T2 D11.C1 D11.C2 D11.F1 D11.F2 D11.N1 D11.N2 D11.T1 D11.T2 D12.C1 D12.C2 D12.F1 D12.F2 D12.N1 D12.N2 D12.T1 D12.T2 D13.C1 D13.C2 D13.F1 D13.F2 D13.N1 D13.N2 D13.T1 D13.T2 D14.C1 D14.C2 D14.F1 D14.F2 D14.N1 D14.N2 D14.T1 D14.T2 GND.1(P) ; also sheet 4
N$10: A01.A1 A02.A1 A03.A1 A04.A1 A05.A1 A06.A1 A07.A1 A08.A1 A09.A1 A10.A1 A11.A1 A12.A1 A13.A1 A14.A1
N$28: A01.B1 A02.B1 A03.B1 A04.B1 A05.B1 A06.B1 A07.B1 A08.B1 A09.B1 A10.B1 A11.B1 A12.B1 A13.B1 A14.B1
N$49: A01.J2 A02.J2 A03.J2 A04.J2 A05.J2 A06.J2 A07.J2 A08.J2 A09.J2 A10.J2 A11.J2 A12.J2 A13.J2 A14.J2
N$62: A01.R1 A02.R1 A03.R1 A04.R1 A05.R1 A06.R1 A07.R1 A08.R1 A09.R1 A10.R1 A11.R1 A12.R1 A13.R1 A14.R1
N$64: A01.S1 A02.S1 A03.S1 A04.S1 A05.S1 A06.S1 A07.S1 A08.S1 A09.S1 A10.S1 A11.S1 A12.S1 A13.S1 A14.S1
N$70: A01.U1 A02.U1 A03.U1 A04.U1 A05.U1 A06.U1 A07.U1 A08.U1 A09.U1 A10.U1 A11.U1 A12.U1 A13.U1 A14.U1
N$72: A01.V1 A02.V1 A03.V1 A04.V1 A05.V1 A06.V1 A07.V1 A08.V1 A09.V1 A10.V1 A11.V1 A12.V1 A13.V1 A14.V1
N$74: A01.V2 A02.V2 A03.V2 A04.V2 A05.V2 A06.V2 A07.V2 A08.V2 A09.V2 A10.V2 A11.V2 A12.V2 A13.V2 A14.V2
N$75: B01.A1 B02.A1 B03.A1 B04.A1 B05.A1 B06.A1 B07.A1 B08.A1 B09.A1 B10.A1 B11.A1 B12.A1 B13.A1 B14.A1
N$77: B01.B1 B02.B1 B03.B1 B04.B1 B05.B1 B06.B1 B07.B1 B08.B1 B09.B1 B10.B1 B11.B1 B12.B1 B13.B1 B14.B1
N$82: B01.D2 B02.D2 B03.D2 B04.D2 B05.D2 B06.D2 B07.D2 B08.D2 B09.D2 B10.D2 B11.D2 B12.D2 B13.D2 B14.D2
N$85: B01.E2 B02.E2 B03.E2 B04.E2 B05.E2 B06.E2 B07.E2 B08.E2 B09.E2 B10.E2 B11.E2 B12.E2 B13.E2 B14.E2
N$89: B01.H2 B02.H2 B03.H2 B04.H2 B05.H2 B06.H2 B07.H2 B08.H2 B09.H2 B10.H2 B11.H2 B12.H2 B13.H2 B14.H2
N$98: B01.J2 B02.J2 B03.J2 B04.J2 B05.J2 B06.J2 B07.J2 B08.J2 B09.J2 B10.J2 B11.J2 B12.J2 B13.J2 B14.J2
N$105: B01.K2 B02.K2 B03.K2 B04.K2 B05.K2 B06.K2 B07.K2 B08.K2 B09.K2 B10.K2 B11.K2 B12.K2 B13.K2 B14.K2
N$107: B01.L2 B02.L2 B03.L2 B04.L2 B05.L2 B06.L2 B07.L2 B08.L2 B09.L2 B10.L2 B11.L2 B12.L2 B13.L2 B14.L2
N$115: B01.M2 B02.M2 B03.M2 B04.M2 B05.M2 B06.M2 B07.M2 B08.M2 B09.M2 B10.M2 B11.M2 B12.M2 B13.M2 B14.M2
N$121: B01.P2 B02.P2 B03.P2 B04.P2 B05.P2 B06.P2 B07.P2 B08.P2 B09.P2 B10.P2 B11.P2 B12.P2 B13.P2 B14.P2
N$123: B01.R1 B02.R1 B03.R1 B04.R1 B05.R1 B06.R1 B07.R1 B08.R1 B09.R1 B10.R1 B11.R1 B12.R1 B13.R1 B14.R1
N$126: B01.R2 B02.R2 B03.R2 B04.R2 B05.R2 B06.R2 B07.R2 B08.R2 B09.R2 B10.R2 B11.R2 B12.R2 B13.R2 B14.R2
N$127: B01.S1 B02.S1 B03.S1 B04.S1 B05.S1 B06.S1 B07.S1 B08.S1 B09.S1 B10.S1 B11.S1 B12.S1 B13.S1 B14.S1
N$130: B01.S2 B02.S2 B03.S2 B04.S2 B05.S2 B06.S2 B07.S2 B08.S2 B09.S2 B10.S2 B11.S2 B12.S2 B13.S2 B14.S2
N$134: B01.U1 B02.U1 B03.U1 B04.U1 B05.U1 B06.U1 B07.U1 B08.U1 B09.U1 B10.U1 B11.U1 B12.U1 B13.U1 B14.U1
N$135: B01.U2 B02.U2 B03.U2 B04.U2 B05.U2 B06.U2 B07.U2 B08.U2 B09.U2 B10.U2 B11.U2 B12.U2 B13.U2 B14.U2
N$136: B01.V1 B02.V1 B03.V1 B04.V1 B05.V1 B06.V1 B07.V1 B08.V1 B09.V1 B10.V1 B11.V1 B12.V1 B13.V1 B14.V1
N$141: C01.A1 C02.A1 C03.A1 C04.A1 C05.A1 C06.A1 C07.A1 C08.A1 C09.A1 C10.A1 C11.A1 C12.A1 C13.A1 C14.A1
N$144: C01.B1 C02.B1 C03.B1 C04.B1 C05.B1 C06.B1 C07.B1 C08.B1 C09.B1 C10.B1 C11.B1 C12.B1 C13.B1 C14.B1
N$154: C01.D1 C02.D1 C03.D1 C04.D1 C05.D1 C06.D1 C07.D1 C08.D1 C09.D1 C10.D1 C11.D1 C12.D1 C13.D1 C14.D1
N$156: C01.D2 C02.D2 C03.D2 C04.D2 C05.D2 C06.D2 C07.D2 C08.D2 C09.D2 C10.D2 C11.D2 C12.D2 C13.D2 C14.D2
N$157: C01.E1 C02.E1 C03.E1 C04.E1 C05.E1 C06.E1 C07.E1 C08.E1 C09.E1 C10.E1 C11.E1 C12.E1 C13.E1 C14.E1
N$158: C01.E2 C02.E2 C03.E2 C04.E2 C05.E2 C06.E2 C07.E2 C08.E2 C09.E2 C10.E2 C11.E2 C12.E2 C13.E2 C14.E2
N$163: C01.H1 C02.H1 C03.H1 C04.H1 C05.H1 C06.H1 C07.H1 C08.H1 C09.H1 C10.H1 C11.H1 C12.H1 C13.H1 C14.H1
N$164: C01.H2 C02.H2 C03.H2 C04.H2 C05.H2 C06.H2 C07.H2 C08.H2 C09.H2 C10.H2 C11.H2 C12.H2 C13.H2 C14.H2
N$165: C01.J1 C02.J1 C03.J1 C04.J1 C05.J1 C06.J1 C07.J1 C08.J1 C09.J1 C10.J1 C11.J1 C12.J1 C13.J1 C14.J1
N$166: C01.J2 C02.J2 C03.J2 C04.J2 C05.J2 C06.J2 C07.J2 C08.J2 C09.J2 C10.J2 C11.J2 C12.J2 C13.J2 C14.J2
N$167: C01.K1 C02.K1 C03.K1 C04.K1 C05.K1 C06.K1 C07.K1 C08.K1 C09.K1 C10.K1 C11.K1 C12.K1 C13.K1 C14.K1
N$168: C01.K2 C02.K2 C03.K2 C04.K2 C05.K2 C06.K2 C07.K2 C08.K2 C09.K2 C10.K2 C11.K2 C12.K2 C13.K2 C14.K2
N$169: C01.L1 C02.L1 C03.L1 C04.L1 C05.L1 C06.L1 C07.L1 C08.L1 C09.L1 C10.L1 C11.L1 C12.L1 C13.L1 C14.L1
N$170: C01.L2 C02.L2 C03.L2 C04.L2 C05.L2 C06.L2 C07.L2 C08.L2 C09.L2 C10.L2 C11.L2 C12.L2 C13.L2 C14.L2
N$171: C01.M1 C02.M1 C03.M1 C04.M1 C05.M1 C06.M1 C07.M1 C08.M1 C09.M1 C10.M1 C11.M1 C12.M1 C13.M1 C14.M1
N$172: C01.M2 C02.M2 C03.M2 C04.M2 C05.M2 C06.M2 C07.M2 C08.M2 C09.M2 C10.M2 C11.M2 C12.M2 C13.M2 C14.M2
N$175: C01.P1 C02.P1 C03.P1 C04.P1 C05.P1 C06.P1 C07.P1 C08.P1 C09.P1 C10.P1 C11.P1 C12.P1 C13.P1 C14.P1
N$176: C01.P2 C02.P2 C03.P2 C04.P2 C05.P2 C06.P2 C07.P2 C08.P2 C09.P2 C10.P2 C11.P2 C12.P2 C13.P2 C14.P2
N$177: C01.R1 C02.R1 C03.R1 C04.R1 C05.R1 C06.R1 C07.R1 C08.R1 C09.R1 C10.R1 C11.R1 C12.R1 C13.R1 C14.R1
N$178: C01.R2 C02.R2 C03.R2 C04.R2 C05.R2 C06.R2 C07.R2 C08.R2 C09.R2 C10.R2 C11.R2 C12.R2 C13.R2 C14.R2
N$179: C01.S1 C02.S1 C03.S1 C04.S1 C05.S1 C06.S1 C07.S1 C08.S1 C09.S1 C10.S1 C11.S1 C12.S1 C13.S1 C14.S1
N$180: C01.S2 C02.S2 C03.S2 C04.S2 C05.S2 C06.S2 C07.S2 C08.S2 C09.S2 C10.S2 C11.S2 C12.S2 C13.S2 C14.S2
N$183: C01.U1 C02.U1 C03.U1 C04.U1 C05.U1 C06.U1 C07.U1 C08.U1 C09.U1 C10.U1 C11.U1 C12.U1 C13.U1 C14.U1
N$184: C01.U2 C02.U2 C03.U2 C04.U2 C05.U2 C06.U2 C07.U2 C08.U2 C09.U2 C10.U2 C11.U2 C12.U2 C13.U2 C14.U2
N$186: C01.V1 C02.V1 C03.V1 C04.V1 C05.V1 C06.V1 C07.V1 C08.V1 C09.V1 C10.V1 C11.V1 C12.V1 C13.V1 C14.V1
N$187: C01.V2 C02.V2 C03.V2 C04.V2 C05.V2 C06.V2 C07.V2 C08.V2 C09.V2 C10.V2 C11.V2 C12.V2 C13.V2 C14.V2
N$188: D01.A1 D02.A1 D03.A1 D04.A1 D05.A1 D06.A1 D07.A1 D08.A1 D09.A1 D10.A1 D11.A1 D12.A1 D13.A1 D14.A1
N$190: D01.B1 D02.B1 D03.B1 D04.B1 D05.B1 D06.B1 D07.B1 D08.B1 D09.B1 D10.B1 D11.B1 D12.B1 D13.B1 D14.B1
N$196: D01.D2 D02.D2 D03.D2 D04.D2 D05.D2 D06.D2 D07.D2 D08.D2 D09.D2 D10.D2 D11.D2 D12.D2 D13.D2 D14.D2
N$198: D01.E2 D02.E2 D03.E2 D04.E2 D05.E2 D06.E2 D07.E2 D08.E2 D09.E2 D10.E2 D11.E2 D12.E2 D13.E2 D14.E2
N$202: D01.H2 D02.H2 D03.H2 D04.H2 D05.H2 D06.H2 D07.H2 D08.H2 D09.H2 D10.H2 D11.H2 D12.H2 D13.H2 D14.H2
N$204: D01.J2 D02.J2 D03.J2 D04.J2 D05.J2 D06.J2 D07.J2 D08.J2 D09.J2 D10.J2 D11.J2 D12.J2 D13.J2 D14.J2
N$206: D01.K2 D02.K2 D03.K2 D04.K2 D05.K2 D06.K2 D07.K2 D08.K2 D09.K2 D10.K2 D11.K2 D12.K2 D13.K2 D14.K2
N$208: D01.L2 D02.L2 D03.L2 D04.L2 D05.L2 D06.L2 D07.L2 D08.L2 D09.L2 D10.L2 D11.L2 D12.L2 D13.L2 D14.L2
N$210: D01.M2 D02.M2 D03.M2 D04.M2 D05.M2 D06.M2 D07.M2 D08.M2 D09.M2 D10.M2 D11.M2 D12.M2 D13.M2 D14.M2
N$214: D01.P2 D02.P2 D03.P2 D04.P2 D05.P2 D06.P2 D07.P2 D08.P2 D09.P2 D10.P2 D11.P2 D12.P2 D13.P2 D14.P2
N$215: D01.R1 D02.R1 D03.R1 D04.R1 D05.R1 D06.R1 D07.R1 D08.R1 D09.R1 D10.R1 D11.R1 D12.R1 D13.R1 D14.R1
N$216: D01.R2 D02.R2 D03.R2 D04.R2 D05.R2 D06.R2 D07.R2 D08.R2 D09.R2 D10.R2 D11.R2 D12.R2 D13.R2 D14.R2
N$218: D01.S2 D02.S2 D03.S2 D04.S2 D05.S2 D06.S2 D07.S2 D08.S2 D09.S2 D10.S2 D11.S2 D12.S2 D13.S2 D14.S2
N$221: D01.U1 D02.U1 D03.U1 D04.U1 D05.U1 D06.U1 D07.U1 D08.U1 D09.U1 D10.U1 D11.U1 D12.U1 D13.U1 D14.U1
N$222: D01.U2 D02.U2 D03.U2 D04.U2 D05.U2 D06.U2 D07.U2 D08.U2 D09.U2 D10.U2 D11.U2 D12.U2 D13.U2 D14.U2
N$223: D01.V1 D02.V1 D03.V1 D04.V1 D05.V1 D06.V1 D07.V1 D08.V1 D09.V1 D10.V1 D11.V1 D12.V1 D13.V1 D14.V1
N$224: D01.V2 D02.V2 D03.V2 D04.V2 D05.V2 D06.V2 D07.V2 D08.V2 D09.V2 D10.V2 D11.V2 D12.V2 D13.V2 D14.V2
VCC [Power]: +5V.1(P) A01.A2 A02.A2 A03.A2 A04.A2 A05.A2 A06.A2 A07.A2 A08.A2 A09.A2 A10.A2 A11.A2 A12.A2 A13.A2 A14.A2 B01.A2 B02.A2 B03.A2 B04.A2 B05.A2 B06.A2 B07.A2 B08.A2 B09.A2 B10.A2 B11.A2 B12.A2 B13.A2 B14.A2 C01.A2 C02.A2 C03.A2 C04.A2 C05.A2 C06.A2 C07.A2 C08.A2 C09.A2 C10.A2 C11.A2 C12.A2 C13.A2 C14.A2 D01.A2 D02.A2 D03.A2 D04.A2 D05.A2 D06.A2 D07.A2 D08.A2 D09.A2 D10.A2 D11.A2 D12.A2 D13.A2 D14.A2

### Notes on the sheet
- A01 thru A14 | B01 thru B14 | C01 thru C14 | D01 thru D14
- Unused Slot:
- Omnibus Memory Connectors
- BM812-I-5

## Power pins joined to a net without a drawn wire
GND: A15.C2(GND) A15.T1(GND) A16.A1 A16.C1 A16.C2 A16.F1 A16.F2 A16.J2 A16.K1 A16.L2 A16.N1 A16.N2 A16.R1 A16.R2 A16.T1 A16.U2 A17N.A1 A17N.C1 A17N.C2 A17N.F1 A17N.F2 A17N.J2 A17N.K1 A17N.L2 A17N.N1 A17N.N2 A17N.R1 A17N.R2 A17N.T1 A17N.U2 A18N.A1 A18N.C1 A18N.C2 A18N.F1 A18N.F2 A18N.J2 A18N.K1 A18N.L2 A18N.N1 A18N.N2 A18N.R1 A18N.R2 A18N.T1 A18N.U2 A19N.A1 A19N.C1 A19N.C2 A19N.F1 A19N.F2 A19N.J2 A19N.K1 A19N.L2 A19N.N1 A19N.N2 A19N.R1 A19N.R2 A19N.T1 A19N.U2 A20N.A1 A20N.C1 A20N.C2 A20N.F1 A20N.F2 A20N.J2 A20N.K1 A20N.L2 A20N.N1 A20N.N2 A20N.R1 A20N.R2 A20N.T1 A20N.U2 B15.C2(GND) B15.T1(GND) B16.C2(GND) B16.T1(GND) B17.C2(GND) B17.T1(GND) B18.C2(GND) B18.T1(GND) B18.U1(GND) B18.V1(GND) B19.C2(GND) B19.T1(GND) B19.U1(GND) B19.V1(GND) B20.C2(GND) B20.T1(GND) B20.U1(GND) B20.V1(GND) C15.C2(GND) C15.T1(GND) C16.C2(GND) C16.T1(GND) C17.C2(GND) C17.T1(GND) C18.C2(GND) C18.T1(GND) C19.C2(GND) C19.T1(GND) C20.C2(GND) C20.T1(GND) D15.C2(GND) D15.T1(GND) D16.C2(GND) D16.T1(GND) D17.C2(GND) D17.T1(GND) D18.C2(GND) D18.T1(GND)
VCC: A15.A2(VCC) B15.A2(VCC) B16.A2(VCC) B17.A2(VCC) B18.A2(VCC) B19.A2(VCC) B20.A2(VCC) C15.A2(VCC) C16.A2(VCC) C17.A2(VCC) C18.A2(VCC) C19.A2(VCC) C20.A2(VCC) D15.A2(VCC) D16.A2(VCC) D17.A2(VCC) D18.A2(VCC)

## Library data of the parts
+5V -15V GND = wirepad:2,54/0,8: THROUGH-HOLE PAD
A01-A09 A10-A14 B01-B09 B10-B14 C01-C09 C10-C14 D01-D09 D10-D14 = dec-m:M916: Simple 36 pin connector/wire cable
A15 B15 C15 C16 = dec-m:M627: 6 4-input NAND Power Amplifier
A16 A17N A18N A19N A20N = dec-m:M903: Two-sided Posibus cable/connector.
B16 = dec-m:M115: 8 3-input NAND Gates
B17 = dec-m:M113: 10 2-input NAND Gates
B18-B20 = dec-m:M623: 6 Dual Bus Drivers
C17 D15-D17 = dec-m:M206X: Two sets of 3 D flip-flops
C18-C20 = dec-m:M310: Tapped Delay Line
D18 = dec-m:M111: Sixteen inverters.
D19 = dec-m:M921
D20 = dec-m:H807: Empty card slot

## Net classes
1 Power: width 0.635 mm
